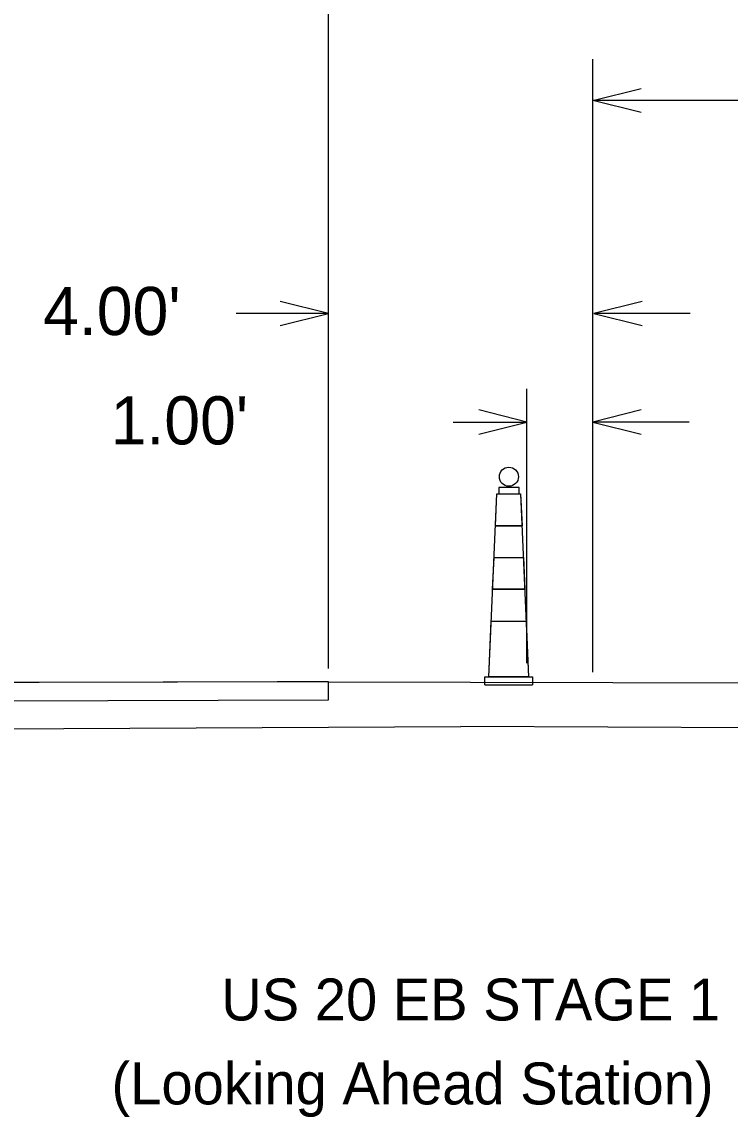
# Model space of a CAD drawing. Extents: x 8410 to 81668, y 7924 to 12712.
# Drawn here: x 11493 to 11827, y 9109 to 9626 of the extents above; entities that cross this region are included whole.
import ezdxf

# ---------------------------------------------------------------- set-up
doc = ezdxf.new("R2010")
doc.units = 0
for name, color, linetype in [('dsnCellElements', 7, 'Continuous'), ('Level 2', 7, 'Continuous'), ('Level 3', 7, 'Continuous')]:
    doc.layers.add(name, color=color, linetype=linetype)

msp = doc.modelspace()

# ---------------------------------------------------------------- linework, layer by layer
at = {"layer": 'dsnCellElements'}
for p, q in [((11713.32, 9316.7), (11717.07, 9402.95)), ((11716.41, 9387.95), (11717.07, 9402.95)), ((11717.07, 9402.95), (11728.32, 9402.95)), ((11717.07, 9402.95), (11728.32, 9402.95)), ((11728.32, 9402.95), (11732.07, 9316.7)), ((11728.32, 9402.95), (11728.97, 9387.95)), ((11716.41, 9387.95), (11728.97, 9387.95)), ((11728.97, 9387.95), (11716.41, 9387.95)), ((11715.11, 9357.95), (11715.76, 9372.95)), ((11715.76, 9372.95), (11729.62, 9372.95)), ((11715.76, 9372.95), (11729.62, 9372.95)), ((11729.62, 9372.95), (11730.27, 9357.95)), ((11715.11, 9357.95), (11730.27, 9357.95)), ((11730.27, 9357.95), (11715.11, 9357.95)), ((11713.32, 9316.7), (11714.46, 9342.95)), ((11714.46, 9342.95), (11730.93, 9342.95)), ((11714.46, 9342.95), (11730.93, 9342.95)), ((11730.93, 9342.95), (11732.07, 9316.7)), ((11711.44, 9316.7), (11733.94, 9316.7)), ((11711.44, 9312.95), (11711.44, 9316.7)), ((11732.07, 9316.7), (11713.32, 9316.7)), ((11733.94, 9316.7), (11733.94, 9312.95)), ((11711.44, 9312.95), (11733.94, 9312.95))]:
    msp.add_line(p, q, dxfattribs=at)
msp.add_lwpolyline([(11727.57, 9405.95), (11717.97, 9405.95), (11717.97, 9402.95), (11727.57, 9402.95)], close=True, dxfattribs=at)
msp.add_circle((11722.77, 9411.05), 4.5, dxfattribs=at)
at = {"layer": 'Level 2'}
for p, q in [((11637.59, 9320.53), (11637.59, 9692.88)), ((11762.45, 9318.87), (11762.45, 9608.03)), ((12137.03, 9588.51), (11762.45, 9588.51)), ((11637.59, 9488.08), (11594.15, 9488.08)), ((11808.33, 9488.08), (11762.91, 9488.08)), ((11731.24, 9323.08), (11731.24, 9452.51)), ((11696.55, 9436.86), (11731.24, 9436.86)), ((11807.87, 9436.86), (11762.45, 9436.86)), ((11134.51, 9290.34), (11700.02, 9293.26)), ((12265.54, 9290.34), (11700.02, 9293.26))]:
    msp.add_line(p, q, dxfattribs=at)
for points in [[(11785.16, 9582.83), (11762.45, 9588.51), (11785.16, 9594.19)], [(11614.88, 9482.4), (11637.59, 9488.08), (11614.88, 9493.76)], [(11785.62, 9493.76), (11762.91, 9488.08), (11785.62, 9482.4)], [(11708.53, 9431.19), (11731.24, 9436.86), (11708.53, 9442.54)], [(11785.16, 9442.54), (11762.45, 9436.86), (11785.16, 9431.19)]]:
    msp.add_lwpolyline(points, dxfattribs=at)
at = {"layer": 'Level 3'}
for p, q in [((11637.59, 9314.37), (11038.81, 9312.64)), ((11637.59, 9314.37), (12361.24, 9312.64)), ((11637.59, 9305.76), (11637.59, 9313.81)), ((11271.71, 9304.65), (11637.59, 9305.76))]:
    msp.add_line(p, q, dxfattribs=at)
msp.add_lwpolyline([(11637.59, 9313.81), (11637.59, 9313.81), (11637.59, 9314.37), (11635.55, 9314.36), (11622.77, 9314.32), (11613.46, 9314.3), (11566.4, 9314.16), (11501.13, 9313.97), (11466.63, 9313.87), (11269.5, 9313.31)], dxfattribs=at)

# ---------------------------------------------------------------- texts
at = {"layer": 'Level 2'}
for s, height, p in [("4.00'", 22.709, (11502.98, 9477.89)), ("1.00'", 22.709, (11534.83, 9426.3)), ('US 20 EB STAGE 1', 19.8, (11587.03, 9154.57)), ('(Looking Ahead Station)', 19.8, (11535.26, 9114.97))]:
    msp.add_text(s, height=height, dxfattribs=at).set_placement(p)

doc.saveas('drawing.dxf')
